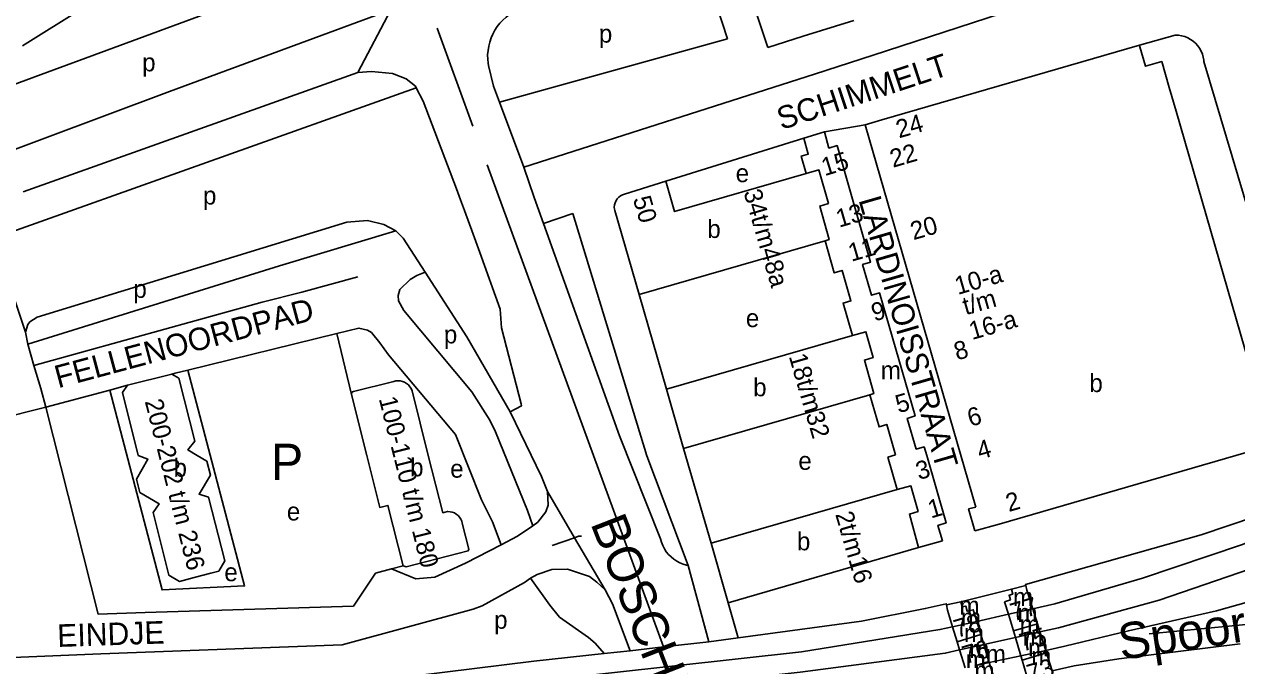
# Model space of a CAD drawing. Extents: x 160673 to 161924, y 382258 to 384145.
# Drawn here: x 160967.8 to 161236.5, y 383703.4 to 383845.5 of the extents above; entities that cross this region are included whole.
import ezdxf

# ---------------------------------------------------------------- set-up
doc = ezdxf.new("R2010")
doc.units = 0
for name, color, linetype in [('BLT_Basislijn', 7, 'Continuous'), ('BLT_Bebouwing', 7, 'Continuous'), ('BLT_Centroide', 7, 'Continuous'), ('BLT_Huisnummer', 7, 'Continuous'), ('BLT_Huisnummer_ tussenligend', 7, 'Continuous'), ('BLT_Huisnummer_reeks', 7, 'Continuous'), ('BLT_Onderverdeling_panden', 7, 'Continuous'), ('BLT_Spoorlijn', 7, 'Continuous'), ('BLT_Straatnaam', 7, 'Continuous'), ('BLT_Straatnaam_hoofdweg', 7, 'Continuous'), ('BLT_Tekst_parkeren', 7, 'Continuous'), ('BLT_Vlakafsluiter', 7, 'Continuous'), ('BLT_Waternaam_spoorwegen', 7, 'Continuous')]:
    doc.layers.add(name, color=color, linetype=linetype)

msp = doc.modelspace()

# ---------------------------------------------------------------- linework, layer by layer
at = {"layer": 'BLT_Basislijn'}
for p, q in [((161037.07, 383858.6), (160962.53, 383831.07)), ((161140.43, 383842.86), (161151.61, 383846.35)), ((161059.26, 383844.68), (161067.21, 383822.96)), ((161222.86, 383843.13), (161214.94, 383840.86)), ((160961.44, 383798.26), (161054.65, 383831.47)), ((161145.09, 383821.68), (161154.14, 383823.22)), ((161140.52, 383820.27), (161109.95, 383810.75)), ((161070.36, 383814.36), (161109.44, 383707.59)), ((161065.33, 383804.29), (161067.26, 383799)), ((161082.85, 383801.42), (161089.34, 383803.57)), ((161105.76, 383749.9), (161089.34, 383803.57)), ((161099.7, 383754.38), (161082.85, 383801.42)), ((161067.26, 383799), (161068.73, 383794.97)), ((160968.05, 383777.33), (160961.69, 383796.15)), ((161029.28, 383786.2), (161041.72, 383789.55)), ((161110.11, 383764.66), (161104.04, 383785.63)), ((160968.05, 383777.33), (160968.58, 383774.65)), ((161037.05, 383777), (161004.07, 383768.92)), ((161040.28, 383763.52), (161037.05, 383777)), ((160968.58, 383774.65), (160969.88, 383769.95)), ((160969.88, 383769.95), (160971.43, 383764.82)), ((160972.61, 383760.74), (160971.43, 383764.82)), ((160986.75, 383764.47), (160972.61, 383760.74)), ((160972.61, 383760.74), (160960.87, 383757.75)), ((161099.7, 383754.38), (161108.77, 383731.54)), ((161105.76, 383749.9), (161114.95, 383725.65)), ((161113.9, 383751.55), (161119.98, 383730.56)), ((161080.49, 383734.4), (161077.1, 383732.12)), ((161077.1, 383732.12), (161073.49, 383730.24)), ((161051.74, 383725.56), (161049.21, 383724.9)), ((161114.95, 383725.65), (161119.47, 383708.72)), ((161040.77, 383716.66), (161045.64, 383723.96)), ((161049.21, 383724.9), (161045.64, 383723.96)), ((161175.35, 383717.61), (161186.54, 383720.41)), ((161123.8, 383717.36), (161125.96, 383709.6)), ((161040.77, 383716.66), (160994.61, 383715.26)), ((161096.3, 383706.12), (161102.08, 383706.77)), ((161102.08, 383706.77), (161109.44, 383707.59)), ((160918.31, 383703.37), (160984.76, 383706.08)), ((161080.72, 383704.46), (161096.3, 383706.12))]:
    msp.add_line(p, q, dxfattribs=at)
for points in [[(161142.93, 383834.49), (161155.9, 383838.64), (161228.49, 383862.34), (161232.13, 383863.24)], [(161125.72, 383860.65), (161127.53, 383854.9), (161128.65, 383852.07), (161130.01, 383848.15), (161132.59, 383840.4)], [(161119.46, 383855.14), (161119.85, 383853.97), (161120.23, 383852.78), (161123.62, 383842.31)], [(161049.06, 383848.75), (161000, 383830.64), (160957.87, 383814.92)], [(161078.73, 383849.3), (161077.83, 383849), (161076.95, 383848.62), (161076.11, 383848.18), (161075.3, 383847.66), (161074.55, 383847.08), (161073.84, 383846.44), (161073.2, 383845.74), (161072.61, 383844.99), (161072.09, 383844.2), (161071.63, 383843.36), (161071.25, 383842.49), (161070.94, 383841.59), (161070.71, 383840.66), (161070.56, 383839.72), (161070.48, 383838.77), (161070.49, 383837.82), (161070.58, 383836.87), (161070.65, 383836.42)], [(161073.09, 383828.27), (161123.62, 383842.31)], [(161132.59, 383840.4), (161140.43, 383842.86)], [(161222.86, 383843.13), (161223.57, 383843.1), (161224.27, 383842.98), (161224.96, 383842.79), (161225.62, 383842.52), (161226.24, 383842.18), (161226.83, 383841.77), (161227.36, 383841.3), (161227.83, 383840.77), (161228.25, 383840.19), (161228.59, 383839.57), (161228.87, 383838.91), (161229.07, 383838.23), (161229.19, 383837.53), (161229.21, 383837.29)], [(161070.65, 383836.42), (161071.81, 383831.8), (161073.09, 383828.27)], [(161229.21, 383837.29), (161246.74, 383778.37), (161249.27, 383771.77), (161252.58, 383765.42), (161258.85, 383744.93)], [(160967.53, 383808.4), (161041.69, 383834.81)], [(161041.69, 383834.81), (161044.74, 383835.03), (161049.4, 383834.63), (161052.41, 383833.42), (161054.47, 383831.81), (161054.65, 383831.47)], [(161142.93, 383834.49), (161078.49, 383813.87)], [(161054.65, 383831.47), (161056.18, 383828.5), (161063.55, 383809.09)], [(161082.85, 383801.42), (161080.81, 383807.12), (161078.49, 383813.87)], [(161063.55, 383809.09), (161064.48, 383806.64), (161065.33, 383804.29)], [(161050.17, 383799.74), (161047.49, 383801.16), (161043.83, 383802.06), (161039.28, 383801.65), (160970.68, 383780.64), (160969.04, 383779.64), (160968.61, 383779.02), (160968.05, 383777.33)], [(160968.58, 383774.65), (161024.38, 383791.99), (161050.17, 383799.74)], [(161050.17, 383799.74), (161051.76, 383798.11), (161056.67, 383790.59)], [(161068.73, 383794.97), (161073.29, 383782.42), (161073.58, 383778.27), (161077.94, 383761.44), (161077.98, 383761), (161075.45, 383759.7)], [(161056.67, 383790.59), (161054.76, 383789.89), (161053.3, 383789.01), (161051.02, 383786.74), (161050.62, 383785.43), (161050.71, 383784.24), (161051.94, 383782.13), (161066.94, 383764.09), (161070.96, 383757.81), (161072.24, 383755.26), (161079.28, 383737.83), (161080.49, 383734.4)], [(161075.45, 383759.7), (161065.84, 383776.28), (161056.67, 383790.59)], [(161029.28, 383786.2), (161020.5, 383783.99), (160969.88, 383769.95)], [(161073.49, 383730.24), (161071.52, 383735.3), (161069.13, 383740.16), (161063.32, 383754.62), (161048.5, 383772.31), (161046.61, 383774.98), (161044.74, 383777.21), (161043.88, 383777.73), (161041.96, 383778.21), (161037.05, 383777)], [(160986.75, 383764.47), (160998.34, 383720.22), (161016.6, 383721.12), (161004.07, 383768.92)], [(161004.07, 383768.92), (161001.21, 383768.22), (161000.53, 383768.04)], [(160990.66, 383765.55), (160986.75, 383764.47)], [(160994.61, 383715.26), (160984.2, 383714.84), (160972.61, 383760.74)], [(161075.45, 383759.7), (161082.44, 383745.34), (161083.76, 383742)], [(161257.81, 383744.45), (161240.64, 383736.52), (161228.63, 383732.4), (161189.65, 383721.41), (161189.71, 383721.22)], [(161083.76, 383742), (161083.87, 383739.01), (161083.38, 383737.52), (161081.6, 383735.26), (161080.49, 383734.4)], [(161084.77, 383730.08), (161089.75, 383731.8)], [(161089.75, 383731.8), (161090.63, 383732.11), (161091.27, 383732.15)], [(161108.77, 383731.54), (161108.98, 383730.78), (161109.27, 383730.05), (161109.64, 383729.35), (161110.07, 383728.7), (161110.57, 383728.09), (161111.12, 383727.53), (161111.73, 383727.03), (161112.39, 383726.6), (161113.09, 383726.24), (161113.82, 383725.94), (161114.58, 383725.73), (161114.95, 383725.65)], [(161049.21, 383724.9), (161054.54, 383722.71), (161058.76, 383723.03), (161065.54, 383726.16), (161073.49, 383730.24)], [(161079.95, 383722.83), (161078.63, 383721.89), (161069.28, 383716.72), (161067.3, 383715.95), (161038.23, 383708.09), (160984.76, 383706.08)], [(161079.95, 383722.83), (161081.48, 383723.66), (161084.67, 383724.75), (161088.18, 383724.82), (161093.05, 383723.23), (161094.71, 383721.96), (161096.54, 383720.24)], [(161079.95, 383722.83), (161084.27, 383716.85), (161086.42, 383714.23), (161092.86, 383709.7), (161094.28, 383708.42), (161096.3, 383706.12)], [(161096.54, 383720.24), (161098.14, 383717.15), (161102.08, 383706.77)], [(161125.96, 383709.6), (161153.31, 383713.31), (161167.46, 383716.11), (161172.12, 383717.17), (161172.17, 383716.91)], [(161119.47, 383708.72), (161125.96, 383709.6)], [(161109.44, 383707.59), (161119.47, 383708.72)], [(160954.18, 383697.13), (161005.83, 383698.79), (161041.27, 383699.58), (161080.72, 383704.46)]]:
    msp.add_lwpolyline(points, dxfattribs=at)
at = {"layer": 'BLT_Bebouwing'}
for p, q in [((161215.04, 383840.52), (161214.94, 383840.86)), ((161223.03, 383826.25), (161221.51, 383831.5)), ((161140.52, 383820.27), (161145.09, 383821.68)), ((161100.82, 383807.91), (161109.95, 383810.75)), ((161104.04, 383785.63), (161098.65, 383804.24)), ((160990.66, 383765.55), (161000.53, 383768.04)), ((161040.73, 383764.16), (161049.7, 383766.42)), ((161040.29, 383763.75), (161040.28, 383763.54)), ((161040.28, 383763.54), (161040.28, 383763.52)), ((161043.68, 383750), (161040.28, 383763.52)), ((161053.73, 383764.34), (161057.33, 383750)), ((161113.9, 383751.55), (161110.11, 383764.66)), ((161159.14, 383749.66), (161160.87, 383750.15)), ((161171.29, 383731.11), (161165.99, 383729.59)), ((161185.88, 383714.84), (161185.05, 383717.62)), ((161186.99, 383711.16), (161185.88, 383714.84)), ((161192.31, 383712.73), (161192.87, 383710.94)), ((161180.41, 383708.15), (161179.74, 383710.37)), ((161187.42, 383709.72), (161186.99, 383711.16)), ((161188.65, 383705.65), (161187.42, 383709.72)), ((161192.87, 383710.94), (161194.15, 383706.84)), ((161174.5, 383708.76), (161175.06, 383706.95)), ((161175.06, 383706.95), (161176.28, 383702.97)), ((161181.56, 383704.39), (161180.41, 383708.15)), ((161194.15, 383706.84), (161194.32, 383706.29)), ((161194.32, 383706.29), (161195.56, 383702.34)), ((161181.64, 383704.13), (161181.56, 383704.39)), ((161183, 383699.64), (161181.64, 383704.13)), ((161188.93, 383704.7), (161188.65, 383705.65)), ((161190, 383701.14), (161188.93, 383704.7))]:
    msp.add_line(p, q, dxfattribs=at)
for points in [[(161214.94, 383840.86), (161157.83, 383824.35), (161154.14, 383823.22)], [(161221.51, 383831.5), (161219.85, 383837.24), (161216.28, 383836.23), (161215.04, 383840.52)], [(161236.29, 383750), (161240.86, 383751.33), (161239.52, 383755.97), (161243.07, 383757), (161223.03, 383826.25)], [(161154.14, 383823.22), (161178.65, 383738.55)], [(161141.08, 383812.48), (161139.99, 383816.32), (161141.52, 383816.76), (161140.52, 383820.27)], [(161145.09, 383821.68), (161146.12, 383818.11), (161147.9, 383818.64), (161155.34, 383792.86), (161153.58, 383792.34), (161155.52, 383785.5), (161157.33, 383786.01), (161165.19, 383758.76), (161163.46, 383758.22), (161165.45, 383751.41), (161167.21, 383751.92), (161167.77, 383750)], [(161141.08, 383812.48), (161111.89, 383804.03), (161109.95, 383810.75)], [(161100.82, 383807.91), (161100.35, 383807.75), (161099.92, 383807.52), (161099.53, 383807.22), (161099.2, 383806.86), (161098.93, 383806.45), (161098.73, 383806), (161098.6, 383805.53), (161098.55, 383805.04), (161098.59, 383804.55), (161098.65, 383804.24)], [(161104.04, 383785.63), (161145.25, 383797.54)], [(161151.34, 383776.57), (161149.26, 383783.75), (161150.99, 383784.24), (161149.02, 383790.99), (161147.3, 383790.45), (161145.25, 383797.54)], [(161151.34, 383776.57), (161110.11, 383764.66)], [(160990.66, 383765.55), (160989.53, 383763.92), (160993.07, 383750)], [(161006.13, 383750), (161004.06, 383751.24), (161005.58, 383753.17), (161002.04, 383767.1), (161000.53, 383768.04)], [(161053.73, 383764.34), (161053.53, 383764.81), (161053.26, 383765.24), (161052.92, 383765.63), (161052.53, 383765.95), (161052.09, 383766.22), (161051.62, 383766.41), (161051.12, 383766.52), (161050.61, 383766.56), (161050.1, 383766.52), (161049.7, 383766.42)], [(161040.73, 383764.16), (161040.53, 383764.08), (161040.38, 383763.94), (161040.29, 383763.75)], [(161113.9, 383751.55), (161155.15, 383763.44)], [(161160.87, 383750.15), (161158.91, 383756.88), (161157.21, 383756.32), (161155.15, 383763.44)], [(161006.13, 383750), (161008.27, 383748.73), (161009.05, 383745.68), (161006.54, 383741.46), (161008.65, 383740.77), (161012.24, 383726.65), (161010.89, 383724.38), (161009.15, 383723.93), (161005.47, 383723), (161002.23, 383722.12), (160999.86, 383723.48), (160996.39, 383737.38), (160997.68, 383739.3), (160993.44, 383741.83), (160992.69, 383744.77), (160995.18, 383749.18), (160993.07, 383750)], [(161043.68, 383750), (161046.58, 383738.49), (161048.37, 383738.95), (161051.74, 383725.56)], [(161061.57, 383737.58), (161060.52, 383737.33), (161057.33, 383750)], [(161161.24, 383742.44), (161159.14, 383749.66)], [(161167.77, 383750), (161172.07, 383735.08), (161170.26, 383734.5), (161171.29, 383731.11)], [(161178.42, 383733.32), (161183.81, 383734.79), (161236.29, 383750)], [(161119.98, 383730.56), (161161.24, 383742.44)], [(161178.65, 383738.55), (161177.04, 383738.18), (161178.42, 383733.32)], [(161064.86, 383734.99), (161064.74, 383735.47), (161064.54, 383735.93), (161064.26, 383736.35), (161063.93, 383736.72), (161063.54, 383737.04), (161063.1, 383737.29), (161062.63, 383737.46), (161062.14, 383737.56), (161061.64, 383737.58), (161061.57, 383737.58)], [(161051.74, 383725.56), (161052.42, 383725.37), (161066.18, 383728.92), (161066.3, 383729.26), (161064.86, 383734.99)], [(161119.98, 383730.56), (161123.8, 383717.36)], [(161123.8, 383717.36), (161165.99, 383729.59)], [(161185.05, 383717.62), (161186.32, 383718), (161186.03, 383719.04), (161186.84, 383719.26), (161186.54, 383720.41)], [(161186.54, 383720.41), (161189.71, 383721.22)], [(161189.71, 383721.22), (161189.98, 383720.16), (161191.27, 383716.04)], [(161175.35, 383717.61), (161172.17, 383716.91), (161172.35, 383715.78), (161173.49, 383712.07)], [(161178.86, 383713.27), (161178.08, 383715.84), (161176.76, 383715.49), (161176.43, 383716.65), (161175.62, 383716.47), (161175.35, 383717.61)], [(161191.27, 383716.04), (161192.31, 383712.73)], [(161173.49, 383712.07), (161174.5, 383708.76)], [(161179.74, 383710.37), (161178.86, 383713.27)]]:
    msp.add_lwpolyline(points, dxfattribs=at)
at = {"layer": 'BLT_Onderverdeling_panden'}
for p, q in [((161186.99, 383711.16), (161192.31, 383712.73)), ((161174.5, 383708.76), (161179.74, 383710.37)), ((161188.93, 383704.7), (161194.32, 383706.29)), ((161181.56, 383704.39), (161178.44, 383703.44))]:
    msp.add_line(p, q, dxfattribs=at)
for points in [[(161145.25, 383797.54), (161146.19, 383797.81), (161144.08, 383805.26), (161146.01, 383805.8), (161143.9, 383813.24), (161141.08, 383812.48)], [(161155.15, 383763.44), (161156.09, 383763.71), (161153.99, 383771.15), (161155.92, 383771.7), (161154.31, 383777.41), (161151.34, 383776.57)], [(161165.99, 383729.59), (161163.93, 383737.03), (161165.86, 383737.57), (161164.28, 383743.28), (161161.24, 383742.44)]]:
    msp.add_lwpolyline(points, dxfattribs=at)
at = {"layer": 'BLT_Spoorlijn'}
for points in [[(161192.87, 383710.94), (161196.97, 383711.86), (161219.32, 383717.97), (161247.05, 383727.49), (161274.96, 383740.09), (161288.32, 383746.56), (161332.02, 383766.76)], [(161298.54, 383755.67), (161262.56, 383739.93), (161237.54, 383730.24), (161215.62, 383722.81), (161196.15, 383717.13), (161191.27, 383716.04)], [(161339.15, 383750.13), (161303.11, 383736.5), (161283.03, 383729.57), (161270.43, 383725.61), (161256.95, 383722.64), (161231.97, 383715.58), (161212.47, 383711.2), (161198.35, 383707.75), (161194.15, 383706.84)], [(161217.08, 383710.52), (161241.63, 383712.9), (161278.05, 383721.01), (161317.67, 383732.56)], [(161185.88, 383714.84), (161178.86, 383713.27)], [(161191.27, 383716.04), (161185.88, 383714.84)], [(161173.49, 383712.07), (161170.71, 383711.45), (161140.01, 383706.48), (161083.88, 383700.28), (161034.33, 383695.48), (160992.74, 383692.56), (160956.62, 383691.24)], [(161178.86, 383713.27), (161173.49, 383712.07)], [(161180.41, 383708.15), (161187.42, 383709.72)], [(161187.42, 383709.72), (161192.87, 383710.94)], [(160957.39, 383684.76), (160992.98, 383686.48), (161034.86, 383690.67), (161083.43, 383695.8), (161139.72, 383702.01), (161171.88, 383706.21), (161175.06, 383706.95)], [(161175.06, 383706.95), (161180.41, 383708.15)], [(161194.15, 383706.84), (161188.65, 383705.65)], [(161195.56, 383702.34), (161200.43, 383703.38), (161210.33, 383704.96), (161237.22, 383708.28)], [(161181.64, 383704.13), (161178.44, 383703.44)], [(161188.65, 383705.65), (161181.64, 383704.13)]]:
    msp.add_lwpolyline(points, dxfattribs=at)
at = {"layer": 'BLT_Vlakafsluiter'}
for p, q in [((160980.74, 383849.05), (160967.37, 383840.75)), ((161049.06, 383848.75), (161041.69, 383834.81)), ((161073.09, 383828.27), (161078.49, 383813.87)), ((161083.76, 383742), (161089.75, 383731.8)), ((161089.75, 383731.8), (161096.54, 383720.24))]:
    msp.add_line(p, q, dxfattribs=at)

# ---------------------------------------------------------------- texts
at = {"layer": 'BLT_Centroide'}
for s, p in [('p', (161095.13, 383841.45)), ('p', (160993.92, 383835.09)), ('e', (161125.45, 383810.55)), ('p', (161007.4, 383805.59)), ('b', (161119.16, 383798.19)), ('p', (160991.97, 383784.91)), ('e', (161127.7, 383778.44)), ('p', (161060.78, 383774.83)), ('m', (161157.6, 383766.9)), ('b', (161203.82, 383764.05)), ('b', (161129.32, 383763.12)), ('b', (161000.88, 383745.28)), ('b', (161053.3, 383745.39)), ('e', (161139.33, 383746.83)), ('e', (161062.18, 383745.09)), ('e', (161025.98, 383735.62)), ('b', (161139.02, 383729)), ('e', (161012.13, 383722.16)), ('m', (161186.9, 383716.68)), ('m', (161175.03, 383714.75)), ('p', (161071.92, 383711.62)), ('m', (161175.36, 383712.13)), ('m', (161187.87, 383713.15)), ('m', (161176.02, 383708.71)), ('m', (161188.38, 383710.63)), ('m', (161189.07, 383707.85)), ('m', (161177.21, 383705.16)), ('m', (161180.86, 383704.06)), ('m', (161190.25, 383705.51)), ('m', (161190.93, 383703.62)), ('m', (161176.42, 383702.9)), ('m', (161178.36, 383700.41))]:
    msp.add_text(s, height=4, dxfattribs=at).set_placement(p)
at = {"layer": 'BLT_Huisnummer'}
for s, p in [('77', (161186.98, 383713.23)), ('78', (161174.47, 383709.58))]:
    msp.add_text(s, height=4, rotation=16.495, dxfattribs=at).set_placement(p)
at = {"layer": 'BLT_Huisnummer_ tussenligend'}
for s, p in [('75', (161189.03, 383706.53)), ('76', (161176.34, 383703.77)), ('73', (161190.67, 383699.67))]:
    msp.add_text(s, height=4, rotation=16.495, dxfattribs=at).set_placement(p)
at = {"layer": 'BLT_Huisnummer_reeks'}
for s, rotation, p in [('24', 16.1606, (161161.64, 383820.24)), ('15', 17.1221, (161145.16, 383811.85)), ('22', 16.1606, (161160.29, 383813.72)), ('34t/m48a', 286.2021, (161127.15, 383808.36)), ('50', 286.0996, (161102.64, 383806.88)), ('13', 16.154, (161148.35, 383800.45)), ('20', 16.1606, (161164.83, 383797.68)), ('11', 16.154, (161151.07, 383792.9)), ('10-a', 16.1261, (161174.66, 383785.56)), ('t/m', 15.7114, (161176.4, 383781.08)), ('9', 16.154, (161156.17, 383779.66)), ('16-a', 16.1285, (161177.82, 383775.57)), ('8', 16.1606, (161174.49, 383771.03)), ('18t/m32', 286.1774, (161137.19, 383771.99)), ('100-110 t/m 180', 284.1199, (161046.34, 383762.58)), ('5', 16.154, (161161.51, 383759.33)), ('200-202 t/m 236', 284.2589, (160994.48, 383762)), ('6', 16.1657, (161177.45, 383756.34)), ('4', 16.1657, (161179.57, 383749.06)), ('3', 16.154, (161166.03, 383744.54)), ('2', 16.1657, (161185.96, 383737.47)), ('1', 16.154, (161168.71, 383736.04)), ('2t/m16', 286.1823, (161147.48, 383737.02))]:
    msp.add_text(s, height=4, rotation=rotation, dxfattribs=at).set_placement(p)
at = {"layer": 'BLT_Straatnaam'}
for s, rotation, p in [('SCHIMMELT', 18.2212, (161135.59, 383822.06)), ('LARDINOISSTRAAT', 286.1609, (161152.63, 383806.62)), ('FELLENOORDPAD', 14.972, (160975.3, 383764.88)), ('EINDJE', 1.8786, (160975.18, 383707.59))]:
    msp.add_text(s, height=5, rotation=rotation, dxfattribs=at).set_placement(p)
at = {"layer": 'BLT_Straatnaam_hoofdweg'}
msp.add_text('BOSCHDIJKTUNNEL', height=7.9999, rotation=291.2945, dxfattribs=at).set_placement((161093.19, 383735.01))
at = {"layer": 'BLT_Tekst_parkeren'}
msp.add_text('P', height=8, dxfattribs=at).set_placement((161022.47, 383744.61))
at = {"layer": 'BLT_Waternaam_spoorwegen'}
msp.add_text('Spoorlijn', height=8, rotation=8.5774, dxfattribs=at).set_placement((161210.86, 383704.69))

doc.saveas('drawing.dxf')
